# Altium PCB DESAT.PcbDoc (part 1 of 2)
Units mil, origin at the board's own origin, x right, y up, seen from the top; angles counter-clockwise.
Board outline 3543.31 x 1895 mil, 4 copper layers (Top Layer, Signal Layer 1, Signal Layer 2, Bottom Layer), stack 40 mil thick; 82 components, 118 nets, 154 pads, 24 vias.
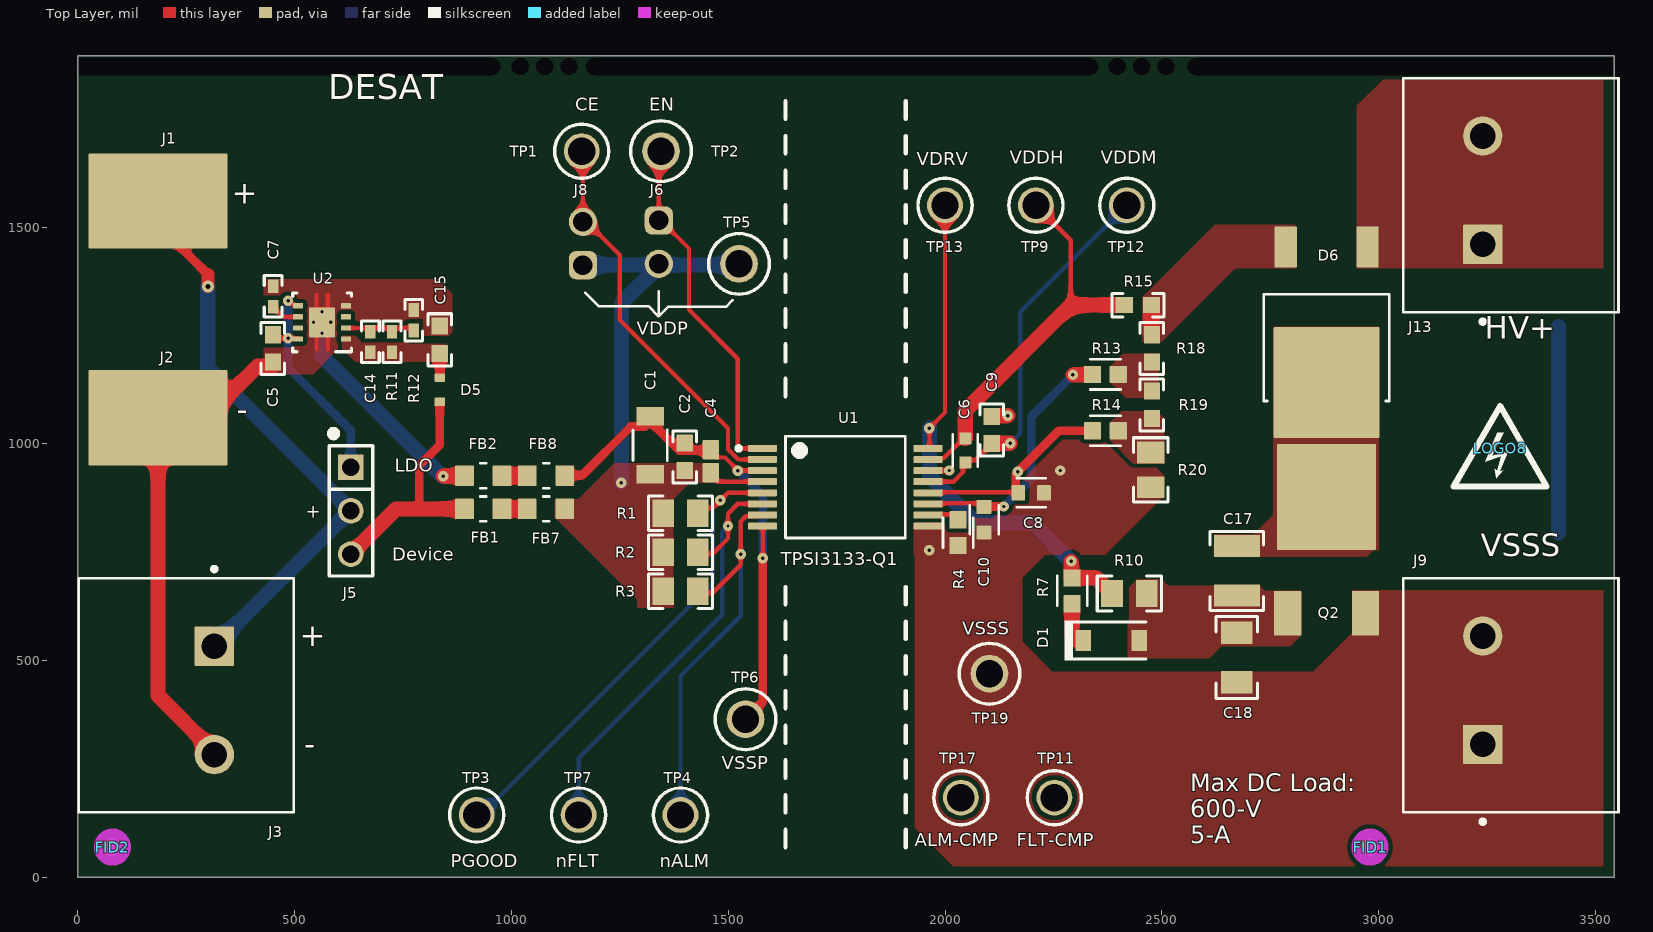
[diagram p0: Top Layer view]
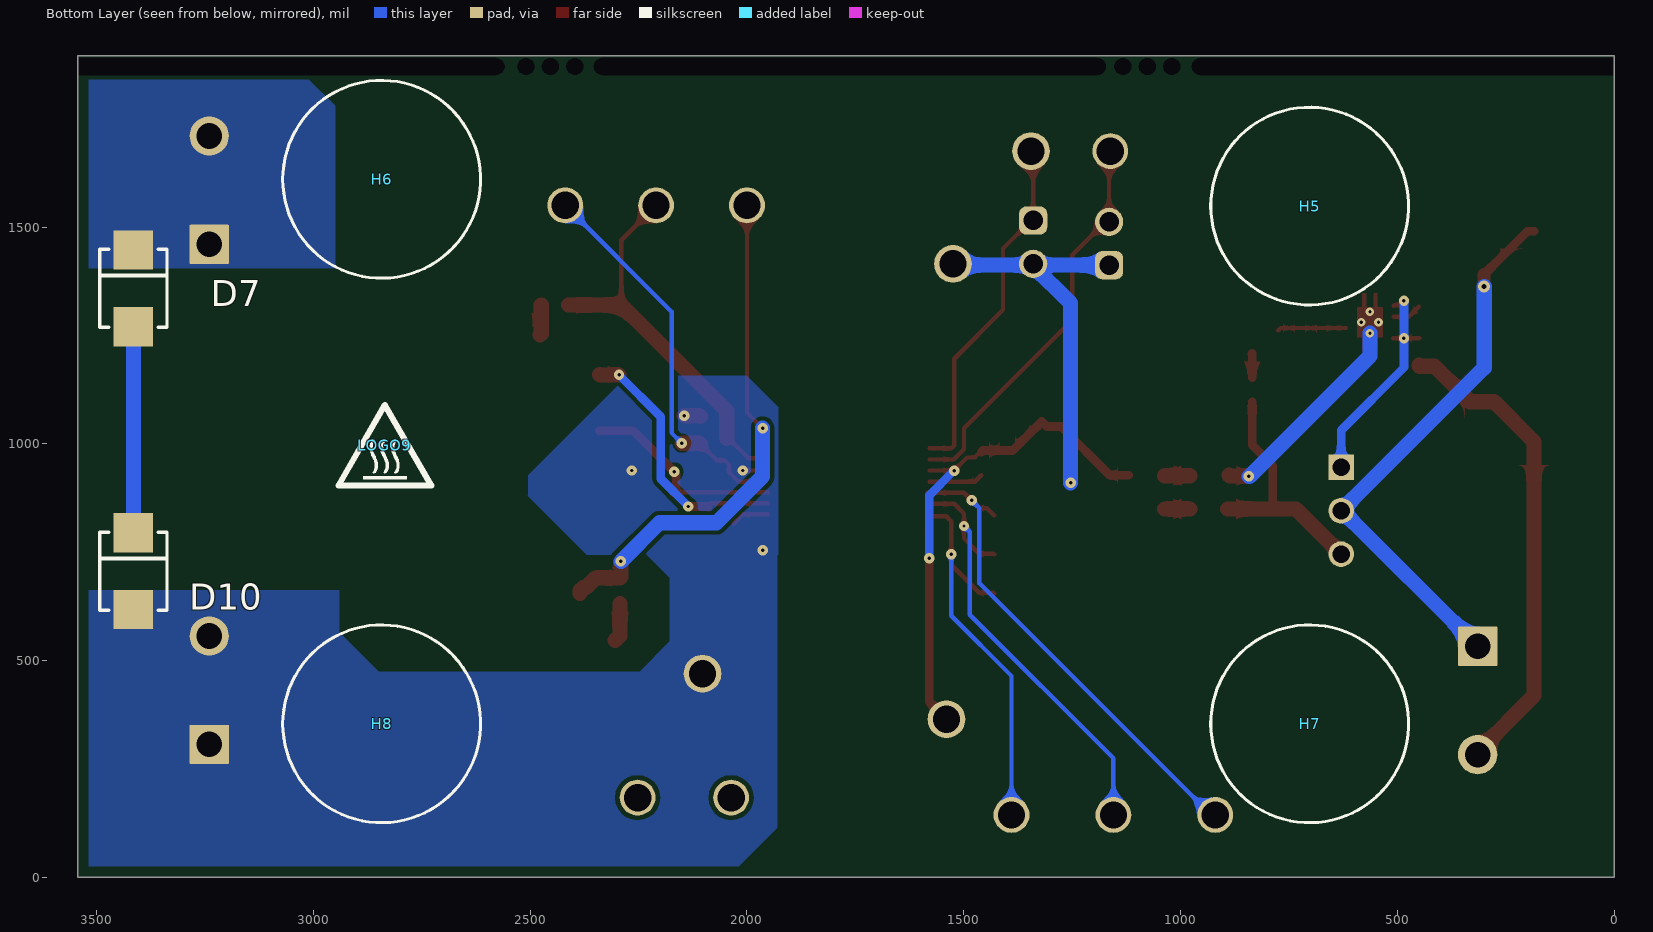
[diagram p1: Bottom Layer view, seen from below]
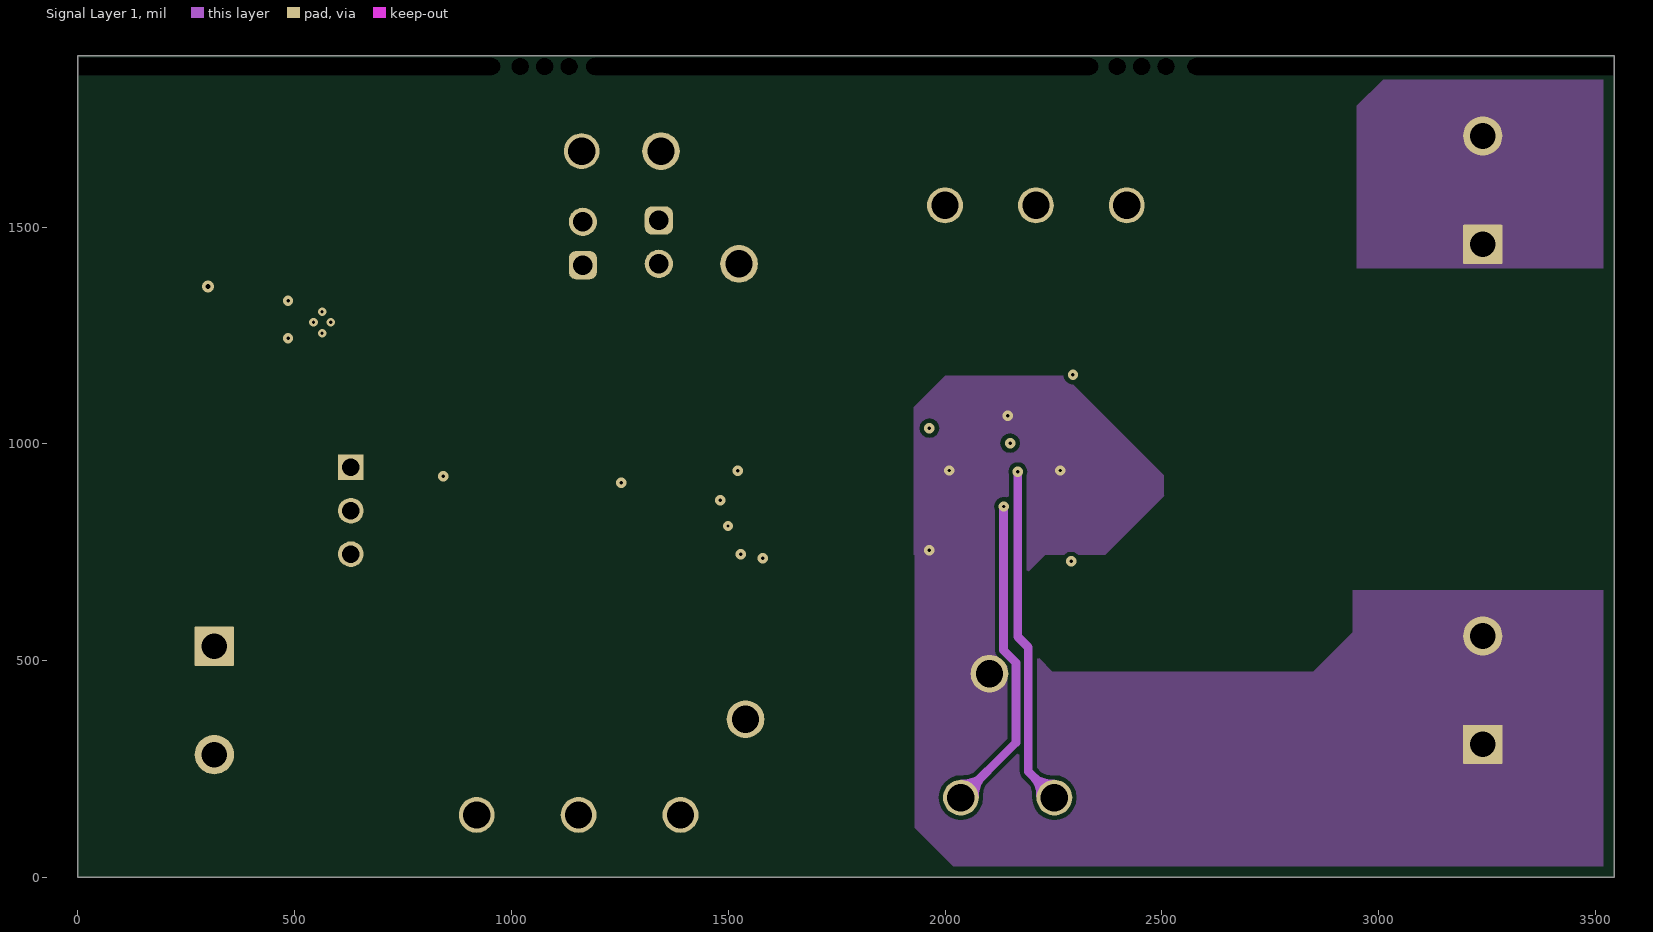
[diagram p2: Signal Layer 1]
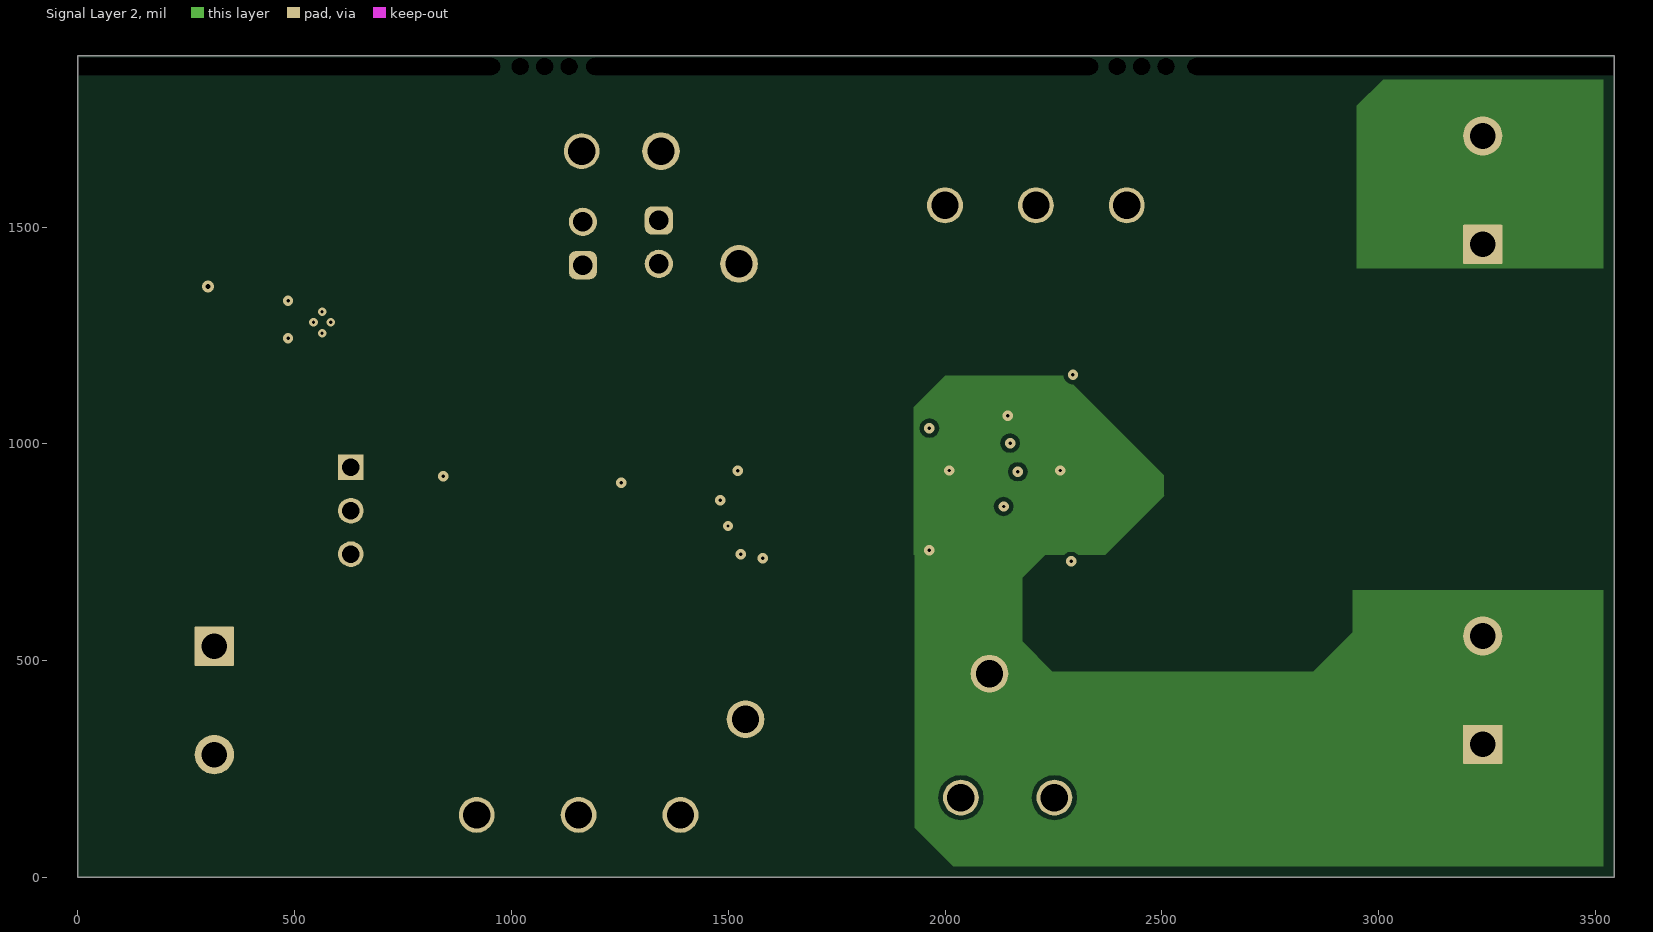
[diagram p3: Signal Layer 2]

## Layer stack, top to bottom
Top Solder: solder mask 0.4, Solder Resist, Dk 3.5
Top Layer: signal copper 2.8
Dielectric 1: prepreg 5, FR-4 High Tg, Dk 4.2
Signal Layer 1: signal copper 1.4
Dielectric 2: core 21.6, FR-4 High Tg, Dk 4.2
Signal Layer 2: signal copper 1.4
Dielectric 3: prepreg 5, FR-4 High Tg, Dk 4.2
Bottom Layer: signal copper 2.8
Bottom Solder: solder mask 0.4, Solder Resist, Dk 3.5

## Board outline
0,0 3543.31,0 3543.31,1895 0,1895

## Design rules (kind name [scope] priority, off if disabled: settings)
AcuteAngle [All] p1: minimum=4.50000000000000E+0001 checktracksonly=FALSE
AssemblyTestPointUsage [All] p1: valid=2
BoardOutlineClearance BoardOutlineClearance_MountingHoles [OnCopper and InComponentClass('Mounting Holes')] p1: gap=39.37 ignorepadtopadclearanceinfootprint=FALSE
BoardOutlineClearance BoardOutlineClearance_Poly [OnCopper and IsPoly] p2: gap=25 ignorepadtopadclearanceinfootprint=FALSE
BoardOutlineClearance [OnCopper and Not InComponentClass('Logo') and not InComponentClass('FiducialMark') and not InRegion(1000,500,4000,800) and not InPoly] p3: gap=40 ignorepadtopadclearanceinfootprint=FALSE
Clearance Clearance_Keepouts [((IsTrack Or IsArc) And Not InPoly) And IsFree and IsKeepOut vs ((IsTrack Or IsArc) And Not InPoly) And IsFree and IsKeepOut] p1: gap=0 ignorepadtopadclearanceinfootprint=FALSE
Clearance Clearance_Poly [InPolygon] p2: gap=10 ignorepadtopadclearanceinfootprint=TRUE
Clearance Clearance_FiducialMark [IsKeepOut and InComponentClass('FiducialMark') vs IsPad and InComponentClass('FiducialMark')] p3: gap=0 ignorepadtopadclearanceinfootprint=FALSE
Clearance [All] p4: gap=7.87 ignorepadtopadclearanceinfootprint=TRUE
ComponentClearance ComponentClearance_MountingHoles_FiducialMarks [InComponentClass('Mounting Holes') vs InComponentClass('FiducialMark')] p1: gap=50 collisioncheckmode=3 verticalgap=10 showdistances=FALSE
ComponentClearance ComponentClearance_Shunt [InComponentClass('Header') vs InComponentClass('Shunt')] p2: gap=0 collisioncheckmode=3 verticalgap=0 showdistances=FALSE
ComponentClearance ComponentClearance_Logo [InComponentClass('Logo')] p3: gap=30 collisioncheckmode=3 verticalgap=10 showdistances=FALSE
ComponentClearance ComponentClearance_ScrewToNut [(HasFootprint('NY PMS 440 0025 PH')) vs (HasFootprint('Keystone_1902C'))] p4: gap=5 collisioncheckmode=3 verticalgap=10 showdistances=FALSE
ComponentClearance ComponentClearance_MountingHoles [InComponentClass('Mounting Holes')] p5: gap=100 collisioncheckmode=3 verticalgap=100000 showdistances=FALSE
ComponentClearance ComponentClearance_SmallPassives [HasFootprint('0201*') or HasFootprint('0402*') or HasFootprint('0508') or HasFootprint('0603*') or HasFootprint('0612') or HasFootprint('0805*') or HasFootprint('0815*') or HasFootprint('0830*') or HasFootprint('1206*') or HasFootprint('1210*') or HasFootprint('1808*') or HasFootprint('1812*') or HasFootprint('1825*') or HasFootprint('2010*') or HasFootprint('2220*') or HasFootprint('2225*') or HasFootprint('2512*') or HasFootprint('2728*') or HasFootprint('3518*') vs HasFootprint('0201*') or HasFootprint('0402*') or HasFootprint('0508') or HasFootprint('0603*') or HasFootprint('0612') or HasFootprint('0805*') or HasFootprint('0815*') or HasFootprint('0830*') or HasFootprint('1206*') or HasFootprint('1210*') or HasFootprint('1808*') or HasFootprint('1812*') or HasFootprint('1825*') or HasFootprint('2010*') or HasFootprint('2220*') or HasFootprint('2225*') or HasFootprint('2512*') or HasFootprint('2728*') or HasFootprint('3518*')] p6: gap=14.96 collisioncheckmode=3 verticalgap=10 showdistances=FALSE
ComponentClearance ComponentClearance_THtoSMT [IsThruComponent vs IsSMTComponent] p7: gap=30 collisioncheckmode=3 verticalgap=30 showdistances=FALSE
ComponentClearance ComponentClearance_THtoTH [IsThruComponent vs IsThruComponent] p8: gap=20 collisioncheckmode=3 verticalgap=30 showdistances=FALSE
ComponentClearance [All] p9: gap=20 collisioncheckmode=3 verticalgap=10 showdistances=FALSE
DiffPairsRouting [All] p1: maxlimit=100 minlimit=10 mostfreqgap=10 toplayer_minwidth=15 toplayer_maxwidth=15 toplayer_prefwidth=15 midlayer1_minwidth=15 midlayer1_maxwidth=15 midlayer1_prefwidth=15 midlayer2_minwidth=15 midlayer2_maxwidth=15 midlayer2_prefwidth=15 bottomlayer_minwidth=15 bottomlayer_maxwidth=15 bottomlayer_prefwidth=15 maxuncoupledlength=1000
FabricationTestPointUsage TestPointUsage [All] p1: valid=2 allowmultiple=FALSE
FabricationTestpoint Testpoint [All] p1: side=3 testpointundercomponent=TRUE minsize=40 maxsize=100 preferedsize=60 minholesize=0 maxholesize=40 preferedholesize=32 testpointgrid=1 allowsidetop=TRUE allowsidebottom=TRUE usegrid=TRUE gridtolerance=0.01
FanoutControl Fanout_LCC [IsLCC] p1: bgadir=Out bgaviamode=Centered fanoutstyle=Auto fanoutdirection=Alternating viagrid=1 // Fanout_LCC (Default Rule)
FanoutControl Fanout_BGA [IsBGA] p2: bgadir=Out bgaviamode=Centered fanoutstyle=Auto fanoutdirection=Alternating viagrid=1 // Fanout_BGA (Default Rule)
FanoutControl Fanout_Default [All] p4: bgadir=Out bgaviamode=Centered fanoutstyle=Auto fanoutdirection=Alternating viagrid=1 // Fanout_Default (Default Rule)
FanoutControl Fanout_Small [(CompPinCount < 5)] p5: bgadir=Out bgaviamode=Centered fanoutstyle=Auto fanoutdirection=OutThenIn viagrid=1 // Fanout_Small (Default Rule)
HoleSize [All] p1: absolutevalues=TRUE maxlimit=251 minlimit=7.87 maxpercent=80.000 minpercent=20.000
MinimumAnnularRing MinimumAnnularRing_ThermalPadVias [IsVia and InAnyComponent] p1: minimumring=5.91
MinimumAnnularRing [All] p2: minimumring=7.87
MinimumSolderMaskSliver MinimumSolderMaskSliver_Logo [InComponentClass('Logo') vs InComponentClass('Logo')] p1: minsoldermaskwidth=0.7
MinimumSolderMaskSliver [All] p2: minsoldermaskwidth=3.94
PlaneConnect [All] p1: planeconnectstyle=Relief reliefexpansion=10 reliefentries=4 reliefconductorwidth=10 reliefairgap=10
PolygonConnect [All] p1: connectstyle=Direct reliefconductorwidth=10 reliefentries=4 polygonreliefangle="90 Angle" airgapwidth=10
RoutingVias ThermalPadVias [IsVia and InAnyComponent] p1: holewidth=7.87 width=19.68 viastyle="Through Hole" minholewidth=7.87 minwidth=19.68 maxholewidth=12.99 maxwidth=23.62
RoutingVias [All] p2: holewidth=16 width=34 viastyle="Through Hole" minholewidth=7.87 minwidth=24 maxholewidth=40 maxwidth=65
SilkToBoardRegionClearance [Not ((IsComment or IsDesignator) And (Hide <> 'False')) and not InRegion(1000,500,4000,800)] p1:
SilkToSilkClearance SilkToSilkClearance_Pb-FreeLogo [(HasFootprint('Pb-Free_Overlay_Medium') OR HasFootprint('Pb-Free_Overlay_Small')) vs (HasFootprint('Pb-Free_Overlay_Medium') OR HasFootprint('Pb-Free_Overlay_Small'))] p1: silktosilkclearance=0
SilkToSilkClearance [All] p2: silktosilkclearance=3.94
SilkToSolderMaskClearance SilkToComponentPadClearance [(IsPad or IsFill or IsRegion) and InAnycomponent] p1: minsilkscreentomaskgap=5 clearancetoexposedcopper=TRUE
SilkToSolderMaskClearance "Silk to Solder Mask Opening" [All] p2: minsilkscreentomaskgap=3.94 clearancetoexposedcopper=FALSE
SolderMaskExpansion [All] p1: expansion=1.97 istentingtop=FALSE
SupplyNets "Schematic Supply Nets_8" [InNet('1VSSS')] p1: voltage=0.000
SupplyNets "Schematic Supply Nets_7" [InNet('4VSSP')] p2: voltage=0.000
SupplyNets "Schematic Supply Nets_6" [InNet('4VDDH')] p3: voltage=0.000
SupplyNets "Schematic Supply Nets_5" [InNet('3VSSP')] p4: voltage=0.000
SupplyNets "Schematic Supply Nets_4" [InNet('4VSSS')] p5: voltage=0.000
SupplyNets "Schematic Supply Nets_3" [InNet('2VSSS')] p6: voltage=0.000
SupplyNets "Schematic Supply Nets_2" [InNet('2VSSP')] p7: voltage=0.000
SupplyNets "Schematic Supply Nets_1" [InNet('1VSSP')] p8: voltage=0.000
SupplyNets "Schematic Supply Nets" [InNet('3VSSS')] p9: voltage=0.000
UnRoutedNet [All] p1: checkbadconnections=TRUE
Width [All] p1: maxlimit=35 minlimit=6 preferedwidth=20 minimp=50.000000 maximp=50.000000 favimp=50.000000 checkconnectedcopper=TRUE
14 further rules are at their usual default settings.

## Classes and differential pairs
component class Shunt: SH-J1 SH-J2 SH-J3 SH-J4 SH-J5 SH-J6 SH-J9 SH-J10 SH-J11 SH-J12
component class Header: J5 J6 J8
component class 4LP111B_DESAT.~(44): C1 C2 C4 C5 C6 C7 C8 C9 C10 C14 C15 C17 C18 D1 D5 D6 D7 D10 FB1 FB2 FB7 FB8 J1 J2 J3 J5 J6 J8 J9 J13 Q2 R1 R2 R3 R4 R7 R10 R11 R12 R13 R14 R15 R18 R19 R20 SH-J1 SH-J2 SH-J3 TP1 TP2 TP3 TP4 TP5 TP6 TP7 TP9 TP11 TP12 TP13 TP17 TP19 U1 U2
component class 3LP111B_Uni-OCP_CSA.~(35): SH-J10 SH-J11 SH-J12
component class 2LP111B_Bi-OCP_noCSA.~(38): SH-J4 SH-J5 SH-J6
component class 1LP111B_Uni-OCP_noCSA.~(35): SH-J9
component class LP111A_Hardware: FID1 FID2 H5 H6 H7 H8 LOGO8 LOGO9 ZZ1 ZZ2 ZZ3 ZZ4
component class FiducialMark: FID1 FID2
component class AssemblyNote: ZZ1 ZZ2 ZZ3 ZZ4

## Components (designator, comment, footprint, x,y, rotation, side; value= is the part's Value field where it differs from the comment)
C1 "C1206C106J3RACAUTO" 1206_180 1320,996.6 r90 top value=10uF
C2 "GCM188R71E105KA64D" 0603 1400,970 r90 top value=1uF
C4 "C0603R104K5RAC" FP-C0603R104K5RAC_0603-IPC_B 1460,960 r270 top
C5 "GRT188R61E106ME13D" 0603 450,1220 r270 top value=10uF
C6 "CGA3E3X7R1E334K080AB" FP-CGA3E3X7R1E334K080AB_0603-MFG 2046.79,984.72 r270 top value=330nF
C7 "GRM155R71E103KA01D" 0402 450.62,1340.04 r90 top value=0.01uF
C8 "CC0603KRX7R7BB102" FP-CC0603KRX7R7BB102_0603-MFG 2198.67,886.99 r180 top value=1nF
C9 "GCM188R71E105KA64D" 0603 2107.72,1032.03 r270 top value=1uF
C10 "CC0603KRX7R7BB102" FP-CC0603KRX7R7BB102_0603-MFG 2090,825 r90 top value=1nF
C14 "GRM155R71E103KA01D" 0402 674.83,1235.04 r90 top value=0.01uF
C15 "GRT188R61E106ME13D" 0603 835,1240 r90 top value=10uF
C17 "GRM32QR72J223KW01L" 1210_150 2672.92,707.14 r270 top value=0.022uF
C18 "GRM31A7U3A101JW31D" 1206 2672.92,507.09 r90 top value=100pF
D1 "MBR0540T1G" SOD-123 2383.1,546.14 r0 top value=40V
D5 "PMEG6002EB,115" FP-PMEG6002EB,115_SOD523-MFG 835,1124.78 r90 top
D6 "C3D03060E" FP-C3D03060E_TO-252-2-MFG 2880,1257.5 r180 top
D7 "824520402" WE-TVSP_DO-214AA_Unidirectional 3415,1358.58 r270 bottom
D10 "824520402" WE-TVSP_DO-214AA_Unidirectional 3415,706.42 r270 bottom
FB1 "BBBK00201209252Y00" FP-BBBK00201209252Y00_0805-MFG 935,850 r0 top
FB2 "BBBK00201209252Y00" FP-BBBK00201209252Y00_0805-MFG 935,926.56 r0 top
FB7 "BBBK00201209252Y00" FP-BBBK00201209252Y00_0805-MFG 1080,850 r0 top
FB8 "BBBK00201209252Y00" FP-BBBK00201209252Y00_0805-MFG 1080,926.56 r0 top
FID1 "Fiducial" Fiducial10-20 2980,70 r0 top
FID2 "Fiducial" Fiducial10-20 80,70 r0 top
H5 "SJ-5303 (CLEAR)" Bumpon_SJ5003Transparent 702.5,1548.19 r180 bottom
H6 "SJ-5303 (CLEAR)" Bumpon_SJ5003Transparent 2842.52,1610 r180 bottom
H7 "SJ-5303 (CLEAR)" Bumpon_SJ5003Transparent 702.5,354.36 r180 bottom
H8 "SJ-5303 (CLEAR)" Bumpon_SJ5003Transparent 2842.52,354.36 r180 bottom
J1 "108-0902-001" Cinch_108-0902-001 0,1560 r0 top
J2 "108-0903-001" Cinch_108-0903-001 0,1060 r0 top
J3 "691250610002" FP-691250610002_CONN_TERM_BLOCK2-MFG 250,420 r270 top
J5 "PEC03SAAN" CONN_PEC03SAAN 629.87,845.72 r270 top
J6 "61300211121" WURTH_61300211121 1340,1465.18 r270 top
J8 "61300211121" WURTH_61300211121 1164.81,1462 r90 top
J9 "691250610002" FP-691250610002_CONN_TERM_BLOCK2-MFG 3304.96,420 r90 top
J13 "691250610002" FP-691250610002_CONN_TERM_BLOCK2-MFG 3304.96,1573.19 r90 top
LOGO8 "DANGER HIGH VOLTAGE" IEC_HighVoltage_Small 3280,990 r0 top
LOGO9 "CAUTION HOT SURFACE" IEC_HotSurface_Small 2835,997.01 r180 bottom
Q2 "STGD10NC60KDT4" DPAK 2880,743.55 r90 top value="600 V"
R1 "ERJ-6GEYJ104V" 0805_HV 1390,840 r0 top value=100k
R2 "ERJ-6GEYJ104V" 0805_HV 1390,750 r0 top value=100k
R3 "ERJ-6GEYJ104V" 0805_HV 1390,660 r0 top value=100k
R4 "WSL060300000ZEA9" FP-WSL060300000ZEA9_0603-MFG 2030,795 r270 top value=0
R7 "WSL060300000ZEA9" FP-WSL060300000ZEA9_0603-MFG 2293.1,661.15 r270 top value=0
R10 "CRCW080510R2FKEA" 0805_HV 2425,655 r0 top value=10.2
R11 "ERJ-2RKF2943X" 0402 724.73,1235.04 r270 top value=294k
R12 "ERJ-2RKF9092X" 0402 775,1285 r270 top value=90.9k
R13 "WSL060300000ZEA9" FP-WSL060300000ZEA9_0603-MFG 2370,1160.02 r0 top value=0
R14 "WSL060300000ZEA9" FP-WSL060300000ZEA9_0603-MFG 2370,1030 r0 top value=0
R15 "CRCW060354K9FKEA" 0603 2444.86,1320 r180 top value=54.9k
R18 "CRCW060320K5FKEA" 0603 2477.12,1220 r90 top value=20.5k
R19 "M55342K12B3E40T" 0603 2477.08,1090 r90 top value=3.40k
R20 "ERJ-6ENF1152V" 0805_HV 2474.57,940 r90 top value=11.5k
SH-J1 "SNT-100-BK-G" SNT-100-BK-G 2710,8110 r90 top value=1x2
SH-J2 "SNT-100-BK-G" SNT-100-BK-G 5301.37,5064.65 r90 top value=1x2
SH-J3 "SNT-100-BK-G" SNT-100-BK-G 6782.87,3934.65 r90 top value=1x2
SH-J4 "SNT-100-BK-G" SNT-100-BK-G 6677.18,5069.3 r90 top value=1x2
SH-J5 "SNT-100-BK-G" SNT-100-BK-G 6281.21,2279.3 r90 top value=1x2
SH-J6 "SNT-100-BK-G" SNT-100-BK-G 4332.39,2279.3 r90 top value=1x2
SH-J9 "SNT-100-BK-G" SNT-100-BK-G 2467.64,8110 r90 top value=1x2
SH-J10 "SNT-100-BK-G" SNT-100-BK-G 5318.91,6151.98 r90 top value=1x2
SH-J11 "SNT-100-BK-G" SNT-100-BK-G 5119.79,4221.98 r90 top value=1x2
SH-J12 "SNT-100-BK-G" SNT-100-BK-G 6168.22,3091.98 r90 top value=1x2
TP1 "5012" KSTN-5012_V 1162.14,1675 r0 top
TP2 "EN" Keystone5014 1345,1675 r90 top
TP3 "5012" KSTN-5012_V 920,144.16 r0 top
TP4 "5012" KSTN-5012_V 1390,144.16 r0 top
TP5 "VDDP" Keystone5010 1525,1415 r0 top
TP6 "5011" Keystone5011 1540,365 r0 top
TP7 "5012" KSTN-5012_V 1155,144.16 r0 top
TP9 "5012" KSTN-5012_V 2209.59,1550 r0 top
TP11 "5012" KSTN-5012_V 2252.1,184.16 r0 top
TP12 "5012" KSTN-5012_V 2419.17,1550 r0 top
TP13 "5012" KSTN-5012_V 2000,1550 r0 top
TP17 "5012" KSTN-5012_V 2036.59,184.16 r0 top
TP19 "5011" Keystone5011 2102.5,470 r0 top
U1 "TPSI3133QDVXRQ1" DVX0016A-MFG 1770,900 r0 top
U2 "TPS7A4901DRBR" DRB0008A 563.38,1280 r180 top
ZZ1 "This Assembly Note is for PCB labels only" AssemblyNoteLabel 0,7880.32 r0 top
ZZ2 "These assemblies are ESD sensitive, ESD precautions shall be observed." AssemblyNote 0,7780.32 r0 top
ZZ3 "These assemblies must be clean and free from flux and all contaminants. Use of no clean flux is not acceptable." AssemblyNote 0,7680.32 r0 top
ZZ4 "These assemblies must comply with workmanship standards IPC-A-610 Class 2, unless otherwise specified." AssemblyNote 0,7580.32 r0 top

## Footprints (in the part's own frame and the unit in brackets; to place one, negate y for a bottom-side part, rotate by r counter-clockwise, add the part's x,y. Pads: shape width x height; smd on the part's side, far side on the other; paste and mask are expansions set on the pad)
0402 [mm] "0402 from SM-752 data"
  rect 0.8x0.6 smd: 1(-0.6,0) 2(0.6,0)
  silkscreen extent -1.22,-0.52 1.22,0.52, body extent -0.55,-0.3 0.55,0.3, height 0.6
0603 [mm] "0603 from SM-752 data"
  rect 1x0.95 smd: 1(-0.8,0) 2(0.8,0)
  silkscreen extent -1.52,-0.69 1.52,0.69, body extent -0.87,-0.47 0.87,0.47, height 1
0805_HV [mil] "0805 with 30mil clearance between pads"
  rect 50x63 smd: 1(-40,0) 2(40,0)
  silkscreen extent -74,-40 74,40, body extent -43,-29 43,29, height 57
1206 [mm] "1206 from SM-752 data"
  rect 1.3x1.85 smd: 1(-1.45,0) 2(1.45,0)
  silkscreen extent -2.4,-1.21 2.4,1.21, body extent -1.7,-0.9 1.7,0.9, height 1.35
1206_180 [mm] "1206_180"
  rect 1.1x1.6 smd: 1(-1.7,0) 2(1.7,0)
  silkscreen extent -0.9,-1 0.9,1, body extent -1.75,-0.95 1.75,0.95, height 1.8
1210_150 [mm] "1210"
  rect 1.3x2.7 smd: 1(-1.45,0) 2(1.45,0)
  silkscreen extent -2.32,-1.57 2.32,1.57, body extent -1.7,-1.35 1.7,1.35, height 1.5
AssemblyNote [mil] "Assembly Note"
AssemblyNoteLabel [mil] "Assembly Note for PCB Labels"
Bumpon_SJ5003Transparent [mil] "3M Hemispherical Bumpon transparent"
  round 1 on Mech4: 0(0,0)
  silkscreen extent -228,-228 228,228, body extent -218,-218 219,218, height 197
Cinch_108-0902-001 [mil] "Banana Jack Insul Nylon Red, TH"
  rrect2% 320x220 smd: 1(185,0)
  body extent -666,-219 272,219, height 232
Cinch_108-0903-001 [mil] "Banana Jack Insul Nylon Black, TH"
  rrect2% 320x220 smd: 1(185,0)
  body extent -666,-219 272,219, height 232
CONN_PEC03SAAN [mm] "SULLINS"
  rect 1.5x1.5 hole 1.016: 1(-2.54,0)
  round 1.5 hole 1.016: 2(0,0) 3(2.54,0)
  silkscreen extent -4.72,-1.27 3.81,1.27, body extent -3.84,-1.3 3.84,1.3, height 8.38
DPAK [mm] "D-PAK, 3-Pads, Body 6.22x6.73mm (max), TO-252AA using nominal STEP model"
  rrect6% 2.6x1.6 smd: 1(-3.4,2.28) 3(-3.4,-2.28)
  rrect2% 6.2x5.8 smd paste-3: 2(3.4,0)
  body extent -3.86,-3.29 5.84,3.29, height 2.48
DRB0008A [mm] "VSON-8"
  rrect32% 0.6x0.31 smd: 1(-1.4,0.975) 2(-1.4,0.325) 3(-1.4,-0.325) 4(-1.4,-0.975) 5(1.4,-0.975) 6(1.4,-0.325) 7(1.4,0.325) 8(1.4,0.975)
  rrect7% 1.5x1.75 smd paste-0.75: 9(0,0)
  Top Layer region: -0.7,-0.875 -0.49,-0.875 -0.471,-0.879 -0.455,-0.89 -0.444,-0.906 -0.44,-0.925 -0.44,-0.925 -0.44,-1.65 -0.436,-1.669 -0.425,-1.685 -0.409,-1.696 -0.39,-1.7 -0.39,-1.7 -0.26,-1.7 -0.241,-1.696 -0.225,-1.685 -0.214,-1.669 -0.21,-1.65 -0.21,-1.65 -0.21,-0.925 -0.206,-0.906 -0.195,-0.89 -0.179,-0.879 -0.16,-0.875 -0.16,-0.875 0.16,-0.875 0.179,-0.879 0.195,-0.89 0.206,-0.906 0.21,-0.925 0.21,-0.925 0.21,-1.65 0.21,-1.65 0.214,-1.669 0.225,-1.685 0.241,-1.696 0.26,-1.7 0.26,-1.7 0.39,-1.7 0.409,-1.696 0.425,-1.685 0.436,-1.669 0.44,-1.65 0.44,-1.65 0.44,-0.925 0.444,-0.906 0.455,-0.89 0.471,-0.879 0.49,-0.875 0.49,-0.875 0.7,-0.875 0.719,-0.871 0.735,-0.86 0.746,-0.844 0.75,-0.825 0.75,-0.825 0.75,0.825 0.746,0.844 0.735,0.86 0.719,0.871 0.7,0.875 0.7,0.875 0.49,0.875 0.471,0.879 0.455,0.89 0.444,0.906 0.44,0.925 0.44,0.925 0.44,1.65 0.436,1.669 0.425,1.685 0.409,1.696 0.39,1.7 0.39,1.7 0.26,1.7 0.241,1.696 0.225,1.685 0.214,1.669 0.21,1.65 0.21,1.65 0.21,1.65 0.21,0.925 0.206,0.906 0.195,0.89 0.179,0.879 0.16,0.875 0.16,0.875 -0.16,0.875 -0.179,0.879 -0.195,0.89 -0.206,0.906 -0.21,0.925 -0.21,0.925 -0.21,1.65 -0.214,1.669 -0.225,1.685 -0.241,1.696 -0.26,1.7 -0.26,1.7 -0.39,1.7 -0.409,1.696 -0.425,1.685 -0.436,1.669 -0.44,1.65 -0.44,1.65 -0.44,0.925 -0.444,0.906 -0.455,0.89 -0.471,0.879 -0.49,0.875 -0.49,0.875 -0.7,0.875 -0.719,0.871 -0.735,0.86 -0.746,0.844 -0.75,0.825 -0.75,0.825 -0.75,-0.825 -0.746,-0.844 -0.735,-0.86 -0.719,-0.871 -0.7,-0.875
  silkscreen extent -1.73,-1.72 1.73,1.72, body extent -1.5,-1.5 1.5,1.5, height 0.77
DVX0016A-MFG [mm] "Recommended Land Pattern"
  rrect24% 1.7x0.41 smd paste+0 mask+0: 1(-4.85,2.275) 2(-4.85,1.625) 3(-4.85,0.975) 4(-4.85,0.325) 5(-4.85,-0.325) 6(-4.85,-0.975) 7(-4.85,-1.625) 8(-4.85,-2.275) 9(4.85,-2.275) 10(4.85,-1.625) 11(4.85,-0.975) 12(4.85,-0.325) 13(4.85,0.325) 14(4.85,0.975) 15(4.85,1.625) 16(4.85,2.275)
  silkscreen extent -6.37,-2.98 3.5,2.98, body extent -5.8,-3.22 5.8,3.22, height 0.25
Fiducial10-20 [mm]
  round 1 smd mask+0.5: 1(0,0)
  Top Layer keep-out circle w1.178: c0,0 r0.5
FP-691250610002_CONN_TERM_BLOCK2-MFG [mm]
  rrect4% 2.3x2.3 hole 1.5 paste-2539.97 mask+0: 1(-2.875,1.65)
  round 2.3 hole 1.5 paste-2539.97 mask+0: 2(3.475,1.65)
  silkscreen extent -7.52,-6.3 6.85,6.3, body extent -6.95,-6.4 6.95,6.4, height 0.25
FP-BBBK00201209252Y00_0805-MFG [mm] "Recommended Land Pattern"
  rrect9% 1.1x1.2 smd paste+0 mask+0: 1(-1.1,0) 2(1.1,0)
  silkscreen extent -0.18,-0.73 0.18,0.73, body extent -1.75,-0.82 1.75,0.82, height 0.25
FP-C3D03060E_TO-252-2-MFG [mm]
  rrect8% 1.3x2.4 smd paste+0 mask+0: 1(-2.39,-5) 2(2.39,-5)
  rrect2% 6.2x6.5 smd paste+0 mask+0: 3(0,2.95)
  silkscreen extent -3.67,-2.22 3.67,4.03, body extent -3.77,-6.3 3.77,6.3, height 0.25
FP-C0603R104K5RAC_0603-IPC_B [mil]
  rrect10% 44.33x37.73 smd paste+0 mask+0: 1(-26.6,0) 2(26.6,0)
  body extent -59,-29 59,29, height 10
FP-CC0603KRX7R7BB102_0603-MFG [mm]
  rrect13% 0.8x0.9 smd paste+0 mask+0: 1(-0.75,0) 2(0.75,0)
  silkscreen extent -0.85,-0.85 0.85,0.85, body extent -1.42,-0.82 1.42,0.82, height 0.25
FP-CGA3E3X7R1E334K080AB_0603-MFG [mm]
  rrect14% 0.7x0.7 smd paste+0 mask+0: 1(-0.7,0) 2(0.7,0)
  silkscreen extent -0.95,-0.73 0.95,0.73, body extent -1.15,-0.65 1.15,0.65, height 0.25
FP-PMEG6002EB,115_SOD523-MFG [mm]
  rrect20% 0.5x0.6 smd paste-1000 mask+0: 1(-0.7,0) 2(0.7,0)
  body extent -1.07,-0.6 1.07,0.6, height 0.25
FP-WSL060300000ZEA9_0603-MFG [mm]
  rrect10% 1.01x1.01 smd paste+0 mask+0: 1(-0.755,0) 2(0.755,0)
  silkscreen extent -0.89,-0.88 0.89,0.88, body extent -1.36,-0.61 1.36,0.61, height 0.25
IEC_HighVoltage_Small [mil]
  silkscreen extent -107,-88 107,97
IEC_HotSurface_Small [mil]
  silkscreen extent -107,-93 107,92
Keystone5010 [mil] "Keystone Multipurpose loops"
  round 87 hole 63: 1(0,0)
  silkscreen extent -70,-70 70,70, body extent -63,-63 63,62, height 319
Keystone5011 [mil] "Keystone Multipurpose loops"
  round 87 hole 63: 1(0,0)
  silkscreen extent -70,-70 70,70, body extent -63,-63 63,62, height 319
Keystone5014 [mil] "Keystone Multipurpose loops"
  round 87 hole 63: 1(0,0)
  silkscreen extent -70,-70 70,70, body extent -63,-63 63,62, height 319
KSTN-5012_V [mm] "Test Point, Dia 3.17mm"
  round 2.1 hole 1.6: 1(0,0)
  silkscreen extent -1.59,-1.58 1.59,1.58, body extent -1.59,-1.59 1.59,1.59, height 8.13
SNT-100-BK-G [mil] "Samtec STEP model"
  round 1 on Mech3: 0(0,0)
  body extent -100,-50 100,50, height 344
SOD-123 [mm] "On Semi recommended land pattern"
  rect 0.915x1.22 smd: 1(-1.637,0) 2(1.637,0)
  silkscreen extent -2.74,-1.17 2.03,1.17, body extent -1.93,-0.9 1.93,0.9, height 1.35
WE-TVSP_DO-214AA_Unidirectional [mm] "Power TVS Diode, 2-Leads. body 4.32x3.62mm"
  rect 2.3x2.3 smd: 1(-2.25,0) 2(2.25,0)
  silkscreen extent -2.28,-1.97 2.28,1.97, body extent -2.7,-1.81 2.7,1.81, height 2.38
WURTH_61300211121 [mm] "Header, 2.54mm, 2x1, TH"
  rrect50% 1.65x1.65 hole 1.15: 1(-1.27,0)
  round 1.65 hole 1.15: 2(1.27,0)
  body extent -2.54,-1.27 2.54,1.27, height 8.54

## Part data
C1: library part CMP-0081062-1, "CAP, CERM, 10 µF, 25 V,+/- 5%, X7R, AEC-Q200 Grade 1, 1206", Cap_Case=1206_180, Manufacturer=Kemet, Supplier Part Number 1=399-15734-1-ND, TempCo=X7R, Tolerance_%=5%, Value2=25V, ValueDisplayed=10µF
C2 C9: library part CMP-0007139-4, "CAP, CERM, 1 uF, 25 V, +/- 10%, X7R, AEC-Q200 Grade 1, 0603", Cap_Case=0603, Manufacturer=MuRata, Supplier Part Number 1=490-10673-1-ND, TempCo=X7R, Tolerance_%=10%, Value1=Unknown, Value2=25V, ValueDisplayed=1uF
C4: library part CMP-0087061-2, "CAP CER 0.1UF 50V X7R 0603", Manufacturer=Kemet, TempCo=15%, Tolerance_%=10%
C5 C15: library part CMP-0007501-1, "CAP, CERM, 10 uF, 25 V, +/- 20%, X5R, 0603", Cap_Case=0603, Manufacturer=MuRata, Supplier Part Number 1=490-12323-1-ND, TempCo=X5R, Tolerance_%=20%, Value1=Unknown, Value2=25V, ValueDisplayed=10uF
C6: library part CMP-0030960-1, "Cap Ceramic 330nF 25V X7R 10% Pad SMD 0603 +125°C Automotive T/R", Manufacturer=TDK, Operating Temperature Range="-55°C to +125°C", TempCo=0.15, Temperature Characteristic=X7R, Tolerance_%=0.1%, ValueDisplayed=330nF
C7 C14: library part CMP-0006658-2, "CAP, CERM, 0.01 uF, 25 V, +/- 10%, X7R, 0402", Cap_Case=0402, Manufacturer=MuRata, Supplier Part Number 1=490-1312-1-ND, TempCo=X7R, Tolerance_%=10%, Value1=Unknown, Value2=25V, ValueDisplayed=0.01uF
C8 C10: library part CMP-0094870-1, "1000 pF ±10% 16V Ceramic Capacitor X7R 0603 (1608 Metric)", Digikey Part Number=311-4063-1-ND, Manufacturer=YAGEO, Mouser Part Number=603-CC603KRX7R7BB102, Operating Temperature Range="-55°C to +125°C", TempCo=15%, Temperature Characteristic=X7R, Tolerance_%=10%, ValueDisplayed="1.0 nF", Voltage=16V
C17: library part CMP-0009248-2, "CAP, CERM, 0.022 uF, 630 V, +/- 10%, X7R, 1210", Cap_Case=1210, Manufacturer=MuRata, Supplier Part Number 1=490-3514-1-ND, TempCo=X7R, Tolerance_%=10%, Value1=Unknown, Value2=630V, ValueDisplayed=0.022uF
C18: library part CMP-0008897-2, "CAP, CERM, 100 pF, 1000 V, +/- 5%, U2J, 1206", Cap_Case=1206, Manufacturer=MuRata, Supplier Part Number 1=490-4301-1-ND, TempCo=U2J, Tolerance_%=5%, Value1=Unknown, Value2=1000V, ValueDisplayed=100pF
D1: library part CMP-0028526-2, "Diode, Schottky, 40 V, 0.5 A, SOD-123", Manufacturer="ON Semiconductor", Value1=0.5A, Value2=0.51V
D5: library part CMP-0087203-1, "DIODE SCHOTTKY 60V 200MA SOD523", Manufacturer=Nexperia
D6: library part CMP-0092653-1, "Diode Silicon Carbide Schottky 600 V 11A (DC) Surface Mount TO-252-2", Digikey Part Number=C3D03060E-ND, Forward Current=11A, Manufacturer=Cree, Max Surge Forward Current=26A, Mouser Part Number=941-C3D03060E, Operating Temperature Range="-55°C to +175°C", Peak Reverse Current=4uA, ValueDisplayed=166pF
D7 D10: library part CMP-03913-133963852-1, "824520402 Tvs Diode, Unidir, 400V, Smb Rohs Compliant: Yes", Leakage Current=1µA, Max Operating Temperature=150°C, Min Operating Temperature=-65°C
FB1 FB2 FB7 FB8: library part CMP-0124406-1, "2.5 kOhms @ 100 MHz 1 Signal Line Ferrite Bead 0805 (2012 Metric) 200mA 700mOhm", Digikey Part Number=553-BBBK00201209252Y00CT-ND, Impedance At Frequency="2500Ω @ 100MHz", Manufacturer="Pulse Electronics", Mouser Part Number=673-BBBK201209252Y00, Operating Temperature Range="-55°C to +125°C", Tolerance_%=25%
FID1 FID2: library part CMP-0077181-1, "Fiducial mark.  There is nothing to buy or mount.", Manufacturer=N/A
H5 H6 H7 H8: library part CMP-0003620-1, "Bumpon, Hemisphere, 0.44 X 0.20, Clear", Manufacturer=3M, Supplier Part Number 1=SJ5303-7-ND
J1: library part CMP-0079575-1, "Banana Jack Insul Nylon Red, TH", Color=Red, Current_A=15A, Manufacturer="Cinch Connectivity", Supplier Part Number 1=J151-ND
J2: library part CMP-0079574-1, "Banana Jack Insul Nylon Black, TH", Color=Black, Current_A=15A, Manufacturer="Cinch Connectivity", Supplier Part Number 1=J152-ND
J3 J9 J13: library part CMP-0093233-2, Current_A=32A, Digikey Part Number=732-691250610002-ND, Manufacturer="Wurth Electronics", Mouser Part Number=710-691250610002, Operating Temperature Range="-32°C to +120°C", Voltage_V=450V
J5: library part CMP-0002338-1, "Header, 100mil, 3x1, Tin, TH", Color=Black, Current_A=3A, Manufacturer="Sullins Connector Solutions", Supplier Part Number 1=S1012E-03-ND, Voltage_V=1.8kV
J6 J8: library part CMP-0054794-2, "Header, 2.54 mm, 2x1, Gold, TH", Color=Black, Manufacturer="Wurth Elektronik", Supplier Part Number 1=732-5315-ND
LOGO8: library part CMP-0074835-1, "IEC 61010-1 High Voltage Warning"
LOGO9: library part CMP-0074837-2, "IEC 61010-1 Hot Surface Warning", Manufacturer="Texas Instruments"
Q2: library part CMP-0000528-4, "Transistor, IGBT, 600 V, 20 A, DPAK", Manufacturer=STMicroelectronics, Value1="20 A"
R1 R2 R3: library part CMP-0020622-3, "RES, 100 k, 5%, 0.125 W, AEC-Q200 Grade 0, 0805", Manufacturer=Panasonic, Power_W=125mW, Supplier Part Number 1=P100KACT-ND, TempCo="200 ppm/C", Tolerance_%=5%, Value2=0.125W, Value_Code=100k
R4 R7 R13 R14: library part CMP-0031931-1, "0 Ohms Jumper Chip Resistor 0603 (1608 Metric) Metal Element", Digikey Part Number=541-3927-1-ND, Manufacturer=Vishay, Mouser Part Number=71-WSL060300000ZEA9, Operating Temperature Range="-65°C to +170°C", TempCo=3900ppm/°C
R10: library part CMP-0020848-3, "RES, 10.2, 1%, 0.125 W, AEC-Q200 Grade 0, 0805", Manufacturer=Vishay-Dale, Power_W=125mW, Supplier Part Number 1=541-10.2CCT-ND, TempCo="100 ppm/C", Tolerance_%=1%, Value2=0.125W, Value_Code=10R2, ValueDisplayed=10.2
R11: library part CMP-0026693-1, "RES, 294 k, 1%, 0.1 W, AEC-Q200 Grade 0, 0402", Manufacturer=Panasonic, Power_W=100mW, Supplier Part Number 1=P294KLCT-ND, TempCo="100 ppm/C", Tolerance_%=1%, Value2=0.1W, Value_Code=294k
R12: library part CMP-0026711-1, "RES, 90.9 k, 1%, 0.1 W, AEC-Q200 Grade 0, 0402", Manufacturer=Panasonic, Power_W=100mW, Supplier Part Number 1=P90.9KLCT-ND, TempCo="100 ppm/C", Tolerance_%=1%, Value2=0.1W, Value_Code=90k9, ValueDisplayed=90.9k
R15: library part CMP-0022494-4, "RES, 54.9 k, 1%, 0.1 W, AEC-Q200 Grade 0, 0603", Manufacturer=Vishay-Dale, Power_W=100mW, Supplier Part Number 1=541-54.9KHCT-ND, TempCo="100 ppm/C", Tolerance_%=1%, Value2=0.1W, Value_Code=54k9, ValueDisplayed=54.9k
R18: library part CMP-0022205-4, "RES, 20.5 k, 1%, 0.1 W, AEC-Q200 Grade 0, 0603", Manufacturer=Vishay-Dale, Power_W=100mW, Supplier Part Number 1=541-20.5KHCT-ND, TempCo="100 ppm/C", Tolerance_%=1%, Value2=0.1W, Value_Code=20k5, ValueDisplayed=20.5k
R19: library part CMP-0080491-1, "RES, 3.40 k, 1%, 0.1 W, 0603", Manufacturer="TT Electronics/IRC", Power_W=100mW, TempCo="100 ppm/C", Tolerance_%=1%, Value2=0.1W, Value_Code=3k40, ValueDisplayed=3.40k
R20: library part CMP-0021540-3, "RES, 11.5 k, 1%, 0.125 W, AEC-Q200 Grade 0, 0805", Manufacturer=Panasonic, Power_W=125mW, Supplier Part Number 1=P11.5KCCT-ND, TempCo="100 ppm/C", Tolerance_%=1%, Value2=0.125W, Value_Code=11k5, ValueDisplayed=11.5k
SH-J1 SH-J2 SH-J3 SH-J4 SH-J5 SH-J6 SH-J9 SH-J10 SH-J11 SH-J12: library part CMP-0003623-3, "Shunt, 100mil, Gold plated, Black", Alternate Manufacturer=3M, Alternate PartNumber=969102-0000-DA, Manufacturer=Samtec, Supplier Part Number 1=SAM8858-ND
TP1 TP3 TP4 TP7 TP9 TP11 TP12 TP13 TP17: library part CMP-1672-00004-4, "Test Point, White, Through Hole, RoHS, Bulk", Colour=White, Manufacturer=Keystone, Package Quantity=100
TP2: library part CMP-0055151-2, "Test Point, Multipurpose, Yellow, TH", Color=Yellow, Manufacturer="Keystone Electronics", PartNumber=5014, Supplier Part Number 1=36-5014-ND
TP5: library part CMP-0055147-2, "Test Point, Multipurpose, Red, TH", Color=Red, Manufacturer="Keystone Electronics", PartNumber=5010, Supplier Part Number 1=36-5010-ND
TP6 TP19: library part CMP-0055148-2, "Test Point, Multipurpose, Black, TH", Color=Black, Manufacturer="Keystone Electronics", Supplier Part Number 1=36-5011-ND
U1: library part CMP-0123884-1, Manufacturer="Texas Instruments", Operating Temperature Range=to
U2: library part CMP-0073868-3, "Vin 3V to 36V, 150mA, Ultra-Low-Noise, High-PSRR Low-Dropout (LDO) Linear Regulator, DRB0008A (VSON-8)", Alternate Manufacturer="Texas Instruments", Alternate PartNumber=TPS7A4901DRBT, Operating Temperature Range="-40 to 125 C", Rating=Catalog
ZZ1: library part CMP-0003616-3
ZZ2: library part CMP-0077236-1
ZZ3: library part CMP-0077237-1
ZZ4: library part CMP-0077238-1

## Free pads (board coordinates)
  round 0 hole 39.37 slot 1181.1 at 0 deg unplated mask+1: 0(383.67,1870.08) 0(1762.77,1870.08)
  round 0 hole 39.37 unplated mask+1: 0(1020.45,1870.08) 0(1076.77,1870.08) 0(1133.09,1870.08) 0(2397.02,1870.08) 0(2453.33,1870.08) 0(2509.65,1870.08)
  round 0 hole 39.37 slot 1200.79 at 0 deg unplated mask+1: 0(3159.26,1870.08)

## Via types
v1: diameter 24, hole 8, Top Layer to Bottom Layer, tented both sides, 19 vias
v2: diameter 19.68, hole 7.87, Top Layer to Bottom Layer, 4 vias
v3: diameter 27.56, hole 11.81, Top Layer to Bottom Layer, tented both sides, 1 vias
